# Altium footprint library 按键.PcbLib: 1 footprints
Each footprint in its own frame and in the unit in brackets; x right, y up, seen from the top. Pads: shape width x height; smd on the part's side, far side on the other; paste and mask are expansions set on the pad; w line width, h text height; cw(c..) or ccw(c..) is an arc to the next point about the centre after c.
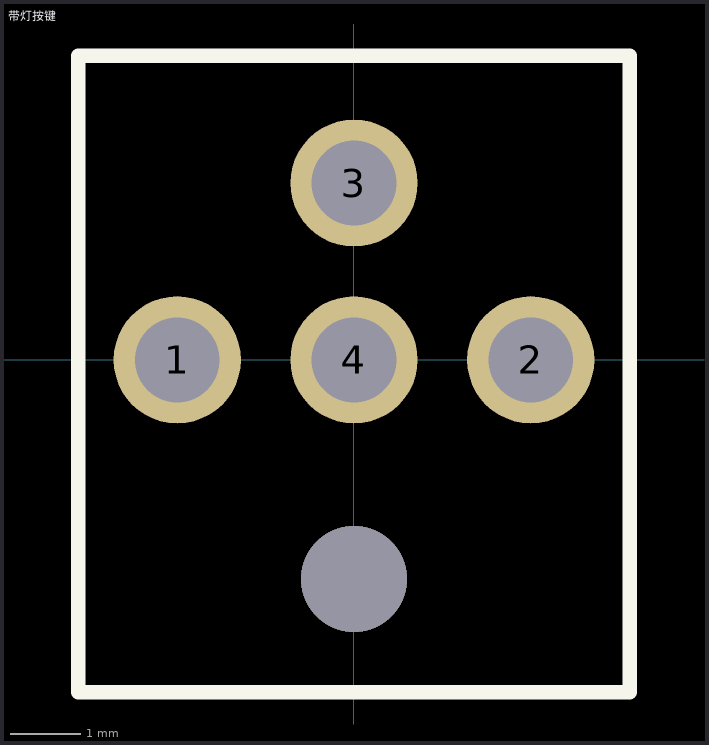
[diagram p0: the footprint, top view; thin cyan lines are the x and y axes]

## 带灯按键 [mm]
pads (4):
  round 1.8 hole 1.2 mask+0.05: 1(-2.5,0) 2(2.5,0) 3(0,2.5) 4(0,0)
via 0,-3.1 diameter 1.5 hole 1.5
Top Overlay:
  lines w0.2: -3.9,-4.7 3.9,-4.7 3.9,4.3 -3.9,4.3 -3.9,-4.7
